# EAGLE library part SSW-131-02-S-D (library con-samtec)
THROUGH-HOLE .025" SQ POST SOCKET Source: Samtec SSW.pdf
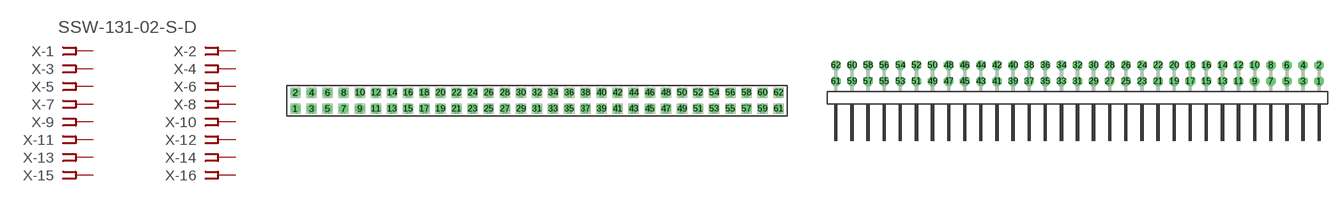
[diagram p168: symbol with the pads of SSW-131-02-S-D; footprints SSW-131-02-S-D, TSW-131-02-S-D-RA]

Designator prefix X; gates -1=FPINV -2=FPIN -3=FPIN -4=FPIN -5=FPIN -6=FPIN -7=FPIN -8=FPIN -9=FPIN -10=FPIN -11=FPIN -12=FPIN -13=FPIN -14=FPIN -15=FPIN -16=FPIN -17=FPIN -18=FPIN -19=FPIN -20=FPIN -21=FPIN -22=FPIN -23=FPIN -24=FPIN -25=FPIN -26=FPIN -27=FPIN -28=FPIN -29=FPIN -30=FPIN -31=FPIN -32=FPIN -33=FPIN -34=FPIN -35=FPIN -36=FPIN -37=FPIN -38=FPIN -39=FPIN -40=FPIN -41=FPIN -42=FPIN -43=FPIN -44=FPIN -45=FPIN -46=FPIN -47=FPIN -48=FPIN -49=FPIN -50=FPIN -51=FPIN -52=FPIN -53=FPIN -54=FPIN -55=FPIN -56=FPIN -57=FPIN -58=FPIN -59=FPIN -60=FPIN -61=FPIN -62=FPIN

## SSW-131-02-S-D (MPN: SSW-131-02-S-D; OC_FARNELL: unknown; OC_NEWARK: 11P9821)  [SSW-131-02-S-D]
1  -1:1  pas
2  -2:1  pas
3  -3:1  pas
4  -4:1  pas
5  -5:1  pas
6  -6:1  pas
7  -7:1  pas
8  -8:1  pas
9  -9:1  pas
10  -10:1  pas
11  -11:1  pas
12  -12:1  pas
13  -13:1  pas
14  -14:1  pas
15  -15:1  pas
16  -16:1  pas
17  -17:1  pas
18  -18:1  pas
19  -19:1  pas
20  -20:1  pas
21  -21:1  pas
22  -22:1  pas
23  -23:1  pas
24  -24:1  pas
25  -25:1  pas
26  -26:1  pas
27  -27:1  pas
28  -28:1  pas
29  -29:1  pas
30  -30:1  pas
31  -31:1  pas
32  -32:1  pas
33  -33:1  pas
34  -34:1  pas
35  -35:1  pas
36  -36:1  pas
37  -37:1  pas
38  -38:1  pas
39  -39:1  pas
40  -40:1  pas
41  -41:1  pas
42  -42:1  pas
43  -43:1  pas
44  -44:1  pas
45  -45:1  pas
46  -46:1  pas
47  -47:1  pas
48  -48:1  pas
49  -49:1  pas
50  -50:1  pas
51  -51:1  pas
52  -52:1  pas
53  -53:1  pas
54  -54:1  pas
55  -55:1  pas
56  -56:1  pas
57  -57:1  pas
58  -58:1  pas
59  -59:1  pas
60  -60:1  pas
61  -61:1  pas
62  -62:1  pas

## SSW-131-02-S-D-RA (MPN: SSW-131-02-S-D-RA; OC_FARNELL: unknown; OC_NEWARK: 11P9822)  [TSW-131-02-S-D-RA]
Pads as for SSW-131-02-S-D

## Footprint SSW-131-02-S-D (pad centres in mm)
THROUGH-HOLE .025" SQ POST SOCKET Source: Samtec SSW.pdf
drill 1 pad 1.5 octagon: 1 -38.1,-1.27; 2 -38.1,1.27; 3 -35.56,-1.27; 4 -35.56,1.27; 5 -33.02,-1.27; 6 -33.02,1.27; 7 -30.48,-1.27; 8 -30.48,1.27; 9 -27.94,-1.27; 10 -27.94,1.27; 11 -25.4,-1.27; 12 -25.4,1.27; 13 -22.86,-1.27; 14 -22.86,1.27; 15 -20.32,-1.27; 16 -20.32,1.27; 17 -17.78,-1.27; 18 -17.78,1.27; 19 -15.24,-1.27; 20 -15.24,1.27; 21 -12.7,-1.27; 22 -12.7,1.27; 23 -10.16,-1.27; 24 -10.16,1.27; 25 -7.62,-1.27; 26 -7.62,1.27; 27 -5.08,-1.27; 28 -5.08,1.27; 29 -2.54,-1.27; 30 -2.54,1.27; 31 0,-1.27; 32 0,1.27; 33 2.54,-1.27; 34 2.54,1.27; 35 5.08,-1.27; 36 5.08,1.27; 37 7.62,-1.27; 38 7.62,1.27; 39 10.16,-1.27; 40 10.16,1.27; 41 12.7,-1.27; 42 12.7,1.27; 43 15.24,-1.27; 44 15.24,1.27; 45 17.78,-1.27; 46 17.78,1.27; 47 20.32,-1.27; 48 20.32,1.27; 49 22.86,-1.27; 50 22.86,1.27; 51 25.4,-1.27; 52 25.4,1.27; 53 27.94,-1.27; 54 27.94,1.27; 55 30.48,-1.27; 56 30.48,1.27; 57 33.02,-1.27; 58 33.02,1.27; 59 35.56,-1.27; 60 35.56,1.27; 61 38.1,-1.27; 62 38.1,1.27

## Footprint TSW-131-02-S-D-RA (pad centres in mm)
THROUGH-HOLE .025" SQ POST HEADER Source: Samtec TSW.pdf
drill 1 pad 1.5 octagon: 1 38.1,1.524; 2 38.1,4.064; 3 35.56,1.524; 4 35.56,4.064; 5 33.02,1.524; 6 33.02,4.064; 7 30.48,1.524; 8 30.48,4.064; 9 27.94,1.524; 10 27.94,4.064; 11 25.4,1.524; 12 25.4,4.064; 13 22.86,1.524; 14 22.86,4.064; 15 20.32,1.524; 16 20.32,4.064; 17 17.78,1.524; 18 17.78,4.064; 19 15.24,1.524; 20 15.24,4.064; 21 12.7,1.524; 22 12.7,4.064; 23 10.16,1.524; 24 10.16,4.064; 25 7.62,1.524; 26 7.62,4.064; 27 5.08,1.524; 28 5.08,4.064; 29 2.54,1.524; 30 2.54,4.064; 31 0,1.524; 32 0,4.064; 33 -2.54,1.524; 34 -2.54,4.064; 35 -5.08,1.524; 36 -5.08,4.064; 37 -7.62,1.524; 38 -7.62,4.064; 39 -10.16,1.524; 40 -10.16,4.064; 41 -12.7,1.524; 42 -12.7,4.064; 43 -15.24,1.524; 44 -15.24,4.064; 45 -17.78,1.524; 46 -17.78,4.064; 47 -20.32,1.524; 48 -20.32,4.064; 49 -22.86,1.524; 50 -22.86,4.064; 51 -25.4,1.524; 52 -25.4,4.064; 53 -27.94,1.524; 54 -27.94,4.064; 55 -30.48,1.524; 56 -30.48,4.064; 57 -33.02,1.524; 58 -33.02,4.064; 59 -35.56,1.524; 60 -35.56,4.064; 61 -38.1,1.524; 62 -38.1,4.064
